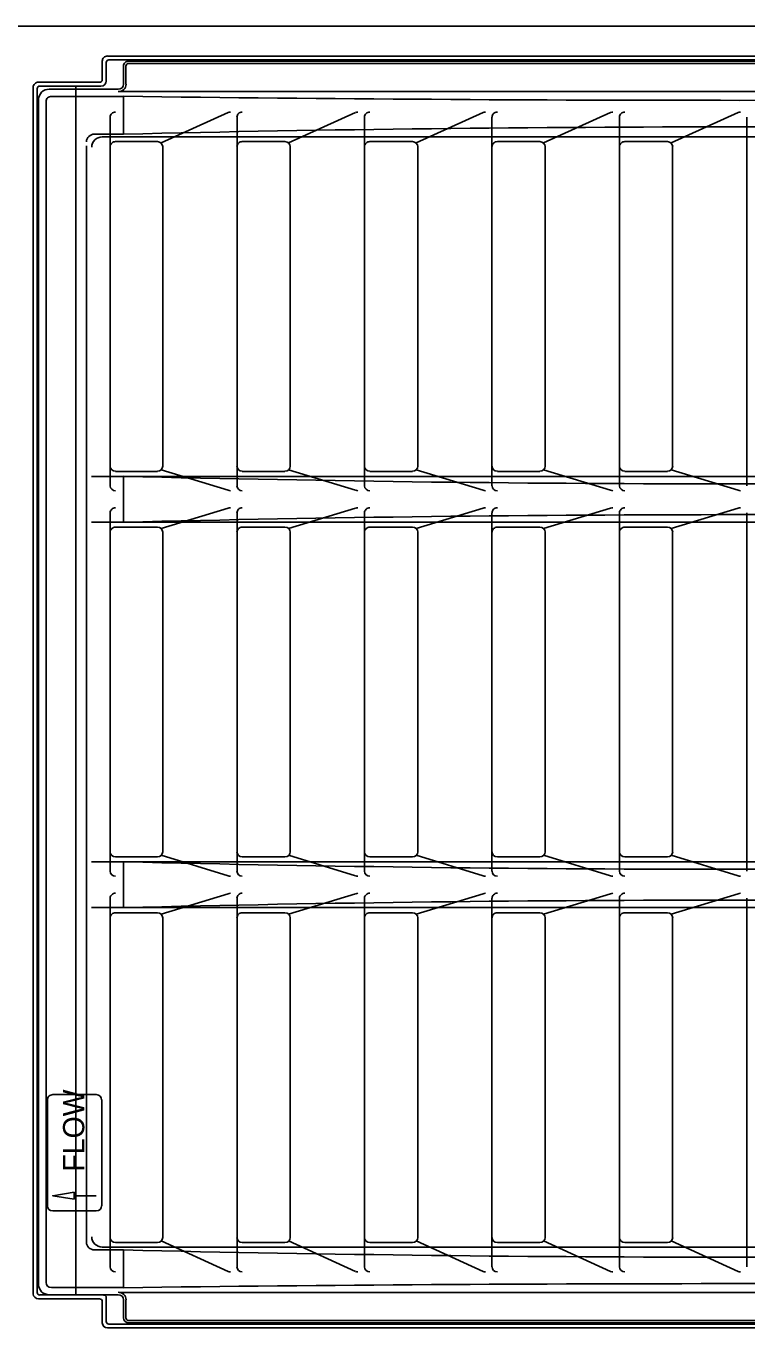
# Model space of a CAD drawing. Extents: x 2.4 to 9.7, y 1.1 to 11.2.
# Drawn here: x 7.421 to 8.009, y 5.384 to 6.445 of the extents above; entities that cross this region are included whole.
import ezdxf

# ---------------------------------------------------------------- set-up
doc = ezdxf.new("R2010")
doc.units = 0
doc.layers.add('DETL-LINE', color=7, linetype='Continuous')
doc.layers.add('DETL-NOTE', color=7, linetype='Continuous')

msp = doc.modelspace()

# ---------------------------------------------------------------- linework, layer by layer
at = {"layer": 'DETL-LINE'}
for p, q in [((7.4498, 6.4451), (6.8316, 6.4451)), ((7.4498, 6.4451), (8.068, 6.4451)), ((7.4831, 6.4013), (7.4831, 6.4166)), ((7.4863, 6.4003), (7.4863, 6.4155)), ((8.5179, 6.4207), (7.4874, 6.4207)), ((8.5168, 6.4176), (7.4885, 6.4176)), ((7.5024, 6.4125), (7.5024, 6.3977)), ((8.5006, 6.4146), (7.5047, 6.4146)), ((7.4268, 5.4117), (7.4268, 6.3952)), ((7.43, 5.4127), (7.43, 6.3941)), ((7.4809, 6.3993), (7.4311, 6.3993)), ((7.482, 6.3962), (7.4322, 6.3962)), ((7.4614, 6.3936), (7.4614, 6.3962)), ((7.4614, 5.4109), (7.4614, 6.3936)), ((8.5092, 6.3917), (7.4969, 6.3917)), ((7.4373, 5.4208), (7.4373, 6.3837)), ((7.5004, 6.3878), (7.4416, 6.3878)), ((7.5004, 6.3878), (7.5004, 6.357)), ((7.4702, 5.4536), (7.4702, 6.3475)), ((7.5004, 6.357), (7.4767, 6.357)), ((7.4831, 6.3547), (8.5222, 6.3547)), ((8.5309, 6.078), (7.4744, 6.078)), ((7.5004, 6.0407), (7.5004, 6.078)), ((8.5309, 6.0407), (7.4744, 6.0407)), ((8.5309, 5.7638), (7.4744, 5.7638)), ((7.5004, 5.7265), (7.5004, 5.7638)), ((8.5309, 5.7265), (7.4744, 5.7265)), ((7.5004, 5.4475), (7.4767, 5.4475)), ((7.4831, 5.4498), (8.5222, 5.4498)), ((7.5004, 5.4167), (7.5004, 5.4475)), ((7.5004, 5.4167), (7.4416, 5.4167)), ((8.5092, 5.4128), (7.4969, 5.4128)), ((7.4809, 5.4076), (7.4311, 5.4076)), ((7.4842, 5.4107), (7.4322, 5.4107)), ((7.4614, 5.4107), (7.4614, 5.4109)), ((7.4831, 5.3879), (7.4831, 5.4055)), ((7.4863, 5.389), (7.4863, 5.4086)), ((7.5024, 5.392), (7.5024, 5.4068)), ((8.5179, 5.3838), (7.4874, 5.3838)), ((8.5168, 5.3869), (7.4885, 5.3869)), ((8.5006, 5.3899), (7.5047, 5.3899))]:
    msp.add_line(p, q, dxfattribs=at)
for centre, major_axis, start_param, end_param in [((7.4874, 6.4166), (0.00433, 0), 1.570796, 3.141593), ((7.4885, 6.4155), (0.00216, 0), 1.570796, 3.141593), ((7.5047, 6.4125), (0.00229, 0), 1.570796, 3.141593), ((7.4809, 6.4013), (0.00216, 0), 4.712389, 6.283185), ((7.482, 6.4003), (0.00433, 0), 4.712389, 6.283185), ((7.4311, 6.3952), (0.00433, 0), 1.570796, 3.141593), ((7.4322, 6.3941), (0.00216, 0), 1.570796, 3.141593), ((7.4961, 6.3977), (0.00637, 0), 4.712389, 6.283185), ((7.4416, 6.3837), (0.00433, 0), 1.570796, 3.141593), ((8.0026, 40.9898), (36.4153, 0), 4.698596, 4.726182), ((8.0026, -12.9443), (20.3171, 0), 1.546073, 1.59552), ((7.4767, 6.3508), (0.00649, 0), 1.570796, 3.141593), ((7.4831, 6.3465), (0.00866, 0), 1.570796, 3.141593), ((8.0026, 24.5302), (19.4238, 0), 4.686528, 4.73825), ((8.0026, -12.4115), (19.4238, 0), 1.544936, 1.596657), ((8.0026, 24.216), (19.4238, 0), 4.686528, 4.73825), ((8.0026, -12.7257), (19.4238, 0), 1.544936, 1.596657), ((7.4831, 5.458), (0.00866, 0), 3.141593, 4.712389), ((7.4767, 5.4536), (0.00649, 0), 3.141593, 4.712389), ((8.0026, 24.7487), (20.3171, 0), 4.687666, 4.737112), ((7.4322, 5.4127), (0.00216, 0), 3.141593, 4.712389), ((7.4416, 5.4208), (0.00433, 0), 3.141593, 4.712389), ((7.4961, 5.4068), (0.00637, 0), 0, 1.570796), ((8.0026, -29.1853), (36.4153, 0), 1.557003, 1.584589), ((7.4311, 5.4117), (0.00433, 0), 3.141593, 4.712389), ((7.4809, 5.4055), (0.00216, 0), 0, 1.570796), ((7.4842, 5.4086), (0.00216, 0), 0, 1.570796), ((7.5047, 5.392), (0.00229, 0), 3.141593, 4.712389), ((7.4874, 5.3879), (0.00433, 0), 3.141593, 4.712389), ((7.4885, 5.389), (0.00216, 0), 3.141593, 4.712389)]:
    msp.add_ellipse(centre, major_axis=major_axis, ratio=0.950294, start_param=start_param, end_param=end_param, dxfattribs=at)
at = {"layer": 'DETL-NOTE'}
for p, q in [((7.5004, 6.4125), (7.5004, 6.3977)), ((7.5047, 6.4166), (8.5006, 6.4166)), ((7.5004, 6.4018), (7.5004, 6.3978)), ((7.4961, 6.3936), (7.4398, 6.3936)), ((7.4311, 5.4191), (7.4311, 6.3854)), ((7.4895, 6.3709), (7.4895, 6.1961)), ((7.5311, 6.3498), (7.5857, 6.3746)), ((7.5929, 6.3709), (7.5929, 6.1961)), ((7.635, 6.3498), (7.6896, 6.3746)), ((7.6968, 6.3709), (7.6968, 6.1961)), ((7.7389, 6.3498), (7.7935, 6.3746)), ((7.8007, 6.3709), (7.8007, 6.1961)), ((7.8428, 6.3498), (7.8974, 6.3746)), ((7.9047, 6.3709), (7.9047, 6.1961)), ((7.9468, 6.3498), (8.0014, 6.3746)), ((8.0086, 6.3709), (8.0086, 6.1961)), ((7.528, 6.351), (7.4938, 6.351)), ((7.5324, 6.3468), (7.5324, 6.1961)), ((7.632, 6.351), (7.5972, 6.351)), ((7.6363, 6.3468), (7.6363, 6.1961)), ((7.7359, 6.351), (7.7012, 6.351)), ((7.7402, 6.3468), (7.7402, 6.1961)), ((7.8398, 6.351), (7.8051, 6.351)), ((7.8441, 6.3468), (7.8441, 6.1961)), ((7.9437, 6.351), (7.909, 6.351)), ((7.948, 6.3468), (7.948, 6.1961)), ((7.4895, 6.0704), (7.4895, 6.1961)), ((7.5324, 6.0863), (7.5324, 6.1961)), ((7.5929, 6.0704), (7.5929, 6.1961)), ((7.6363, 6.0863), (7.6363, 6.1961)), ((7.6968, 6.0704), (7.6968, 6.1961)), ((7.7402, 6.0863), (7.7402, 6.1961)), ((7.8007, 6.0704), (7.8007, 6.1961)), ((7.8441, 6.0863), (7.8441, 6.1961)), ((7.9047, 6.0704), (7.9047, 6.1961)), ((7.948, 6.0863), (7.948, 6.1961)), ((8.0086, 6.0704), (8.0086, 6.1961)), ((7.528, 6.0821), (7.4938, 6.0821)), ((7.5311, 6.0834), (7.5857, 6.0667)), ((7.632, 6.0821), (7.5972, 6.0821)), ((7.635, 6.0834), (7.6896, 6.0667)), ((7.7359, 6.0821), (7.7012, 6.0821)), ((7.7389, 6.0834), (7.7935, 6.0667)), ((7.8398, 6.0821), (7.8051, 6.0821)), ((7.8428, 6.0834), (7.8974, 6.0667)), ((7.9437, 6.0821), (7.909, 6.0821)), ((7.9468, 6.0834), (8.0014, 6.0667)), ((7.5311, 6.0354), (7.5857, 6.0521)), ((7.635, 6.0354), (7.6896, 6.0521)), ((7.7389, 6.0354), (7.7935, 6.0521)), ((7.8428, 6.0354), (7.8974, 6.0521)), ((7.9468, 6.0354), (8.0014, 6.0521)), ((7.4895, 6.0483), (7.4895, 5.7561)), ((7.5929, 6.0483), (7.5929, 5.7561)), ((7.6968, 6.0483), (7.6968, 5.7561)), ((7.8007, 6.0483), (7.8007, 5.7561)), ((7.9047, 6.0483), (7.9047, 5.7561)), ((8.0086, 6.0483), (8.0086, 5.7561)), ((7.528, 6.0366), (7.4938, 6.0366)), ((7.5324, 6.0325), (7.5324, 5.772)), ((7.632, 6.0366), (7.5972, 6.0366)), ((7.6363, 6.0325), (7.6363, 5.772)), ((7.7359, 6.0366), (7.7012, 6.0366)), ((7.7402, 6.0325), (7.7402, 5.772)), ((7.8398, 6.0366), (7.8051, 6.0366)), ((7.8441, 6.0325), (7.8441, 5.772)), ((7.9437, 6.0366), (7.909, 6.0366)), ((7.948, 6.0325), (7.948, 5.772)), ((7.528, 5.7679), (7.4938, 5.7679)), ((7.5311, 5.7691), (7.5857, 5.7524)), ((7.632, 5.7679), (7.5972, 5.7679)), ((7.635, 5.7691), (7.6896, 5.7524)), ((7.7359, 5.7679), (7.7012, 5.7679)), ((7.7389, 5.7691), (7.7935, 5.7524)), ((7.8398, 5.7679), (7.8051, 5.7679)), ((7.8428, 5.7691), (7.8974, 5.7524)), ((7.9437, 5.7679), (7.909, 5.7679)), ((7.9468, 5.7691), (8.0014, 5.7524)), ((7.4895, 5.7341), (7.4895, 5.703)), ((7.5311, 5.7211), (7.5857, 5.7378)), ((7.5929, 5.7341), (7.5929, 5.703)), ((7.635, 5.7211), (7.6896, 5.7378)), ((7.6968, 5.7341), (7.6968, 5.703)), ((7.7389, 5.7211), (7.7935, 5.7378)), ((7.8007, 5.7341), (7.8007, 5.703)), ((7.8428, 5.7211), (7.8974, 5.7378)), ((7.9047, 5.7341), (7.9047, 5.703)), ((7.9468, 5.7211), (8.0014, 5.7378)), ((8.0086, 5.7341), (8.0086, 5.703)), ((7.528, 5.7223), (7.4938, 5.7223)), ((7.632, 5.7223), (7.5972, 5.7223)), ((7.7359, 5.7223), (7.7012, 5.7223)), ((7.8398, 5.7223), (7.8051, 5.7223)), ((7.9437, 5.7223), (7.909, 5.7223)), ((7.5324, 5.7182), (7.5324, 5.703)), ((7.6363, 5.7182), (7.6363, 5.703)), ((7.7402, 5.7182), (7.7402, 5.703)), ((7.8441, 5.7182), (7.8441, 5.703)), ((7.948, 5.7182), (7.948, 5.703)), ((7.4895, 5.4336), (7.4895, 5.703)), ((7.5324, 5.4576), (7.5324, 5.703)), ((7.5929, 5.4336), (7.5929, 5.703)), ((7.6363, 5.4576), (7.6363, 5.703)), ((7.6968, 5.4336), (7.6968, 5.703)), ((7.7402, 5.4576), (7.7402, 5.703)), ((7.8007, 5.4336), (7.8007, 5.703)), ((7.8441, 5.4576), (7.8441, 5.703)), ((7.9047, 5.4336), (7.9047, 5.703)), ((7.948, 5.4576), (7.948, 5.703)), ((8.0086, 5.4336), (8.0086, 5.703)), ((7.4427, 5.574), (7.4782, 5.574)), ((7.4384, 5.5699), (7.4384, 5.4834)), ((7.4826, 5.5699), (7.4826, 5.4834)), ((7.4601, 5.4916), (7.478, 5.4916)), ((7.4427, 5.4793), (7.4782, 5.4793)), ((7.528, 5.4535), (7.4938, 5.4535)), ((7.5311, 5.4547), (7.5857, 5.4298)), ((7.632, 5.4535), (7.5972, 5.4535)), ((7.635, 5.4547), (7.6896, 5.4298)), ((7.7359, 5.4535), (7.7012, 5.4535)), ((7.7389, 5.4547), (7.7935, 5.4298)), ((7.8398, 5.4535), (7.8051, 5.4535)), ((7.8428, 5.4547), (7.8974, 5.4298)), ((7.9437, 5.4535), (7.909, 5.4535)), ((7.9468, 5.4547), (8.0014, 5.4298)), ((7.4961, 5.4109), (7.4398, 5.4109)), ((7.5004, 5.392), (7.5004, 5.4068)), ((7.5004, 5.4027), (7.5004, 5.4067)), ((7.5047, 5.3879), (8.5006, 5.3879))]:
    msp.add_line(p, q, dxfattribs=at)
msp.add_lwpolyline([(7.4601, 5.4889), (7.4601, 5.4944), (7.4427, 5.4916)], close=True, dxfattribs=at)
for centre, major_axis, start_param, end_param in [((7.5047, 6.4125), (0.00433, 0), 1.570796, 3.141593), ((7.4398, 6.3854), (0.00866, 0), 1.570796, 3.141593), ((7.4961, 6.3977), (0.00433, 0), 4.712389, 6.283185), ((7.4938, 6.3709), (0.00433, 0), 1.570796, 3.141593), ((7.5876, 6.3709), (0.00433, 0), 1.570796, 2.018093), ((7.5972, 6.3709), (0.00433, 0), 1.570796, 3.141593), ((7.6915, 6.3709), (0.00433, 0), 1.570796, 2.018093), ((7.7012, 6.3709), (0.00433, 0), 1.570796, 3.141593), ((7.7954, 6.3709), (0.00433, 0), 1.570796, 2.018093), ((7.8051, 6.3709), (0.00433, 0), 1.570796, 3.141593), ((7.8993, 6.3709), (0.00433, 0), 1.570796, 2.018093), ((7.909, 6.3709), (0.00433, 0), 1.570796, 3.141593), ((8.0032, 6.3709), (0.00433, 0), 1.570796, 2.018093), ((7.4938, 6.3468), (0.00433, 0), 1.570796, 3.141593), ((7.528, 6.3468), (0.00433, 0), 0, 1.570796), ((7.5972, 6.3468), (0.00433, 0), 1.570796, 3.141593), ((7.632, 6.3468), (0.00433, 0), 0, 1.570796), ((7.7012, 6.3468), (0.00433, 0), 1.570796, 3.141593), ((7.7359, 6.3468), (0.00433, 0), 0, 1.570796), ((7.8051, 6.3468), (0.00433, 0), 1.570796, 3.141593), ((7.8398, 6.3468), (0.00433, 0), 0, 1.570796), ((7.909, 6.3468), (0.00433, 0), 1.570796, 3.141593), ((7.9437, 6.3468), (0.00433, 0), 0, 1.570796), ((7.4938, 6.0863), (0.00433, 0), 3.141593, 4.712389), ((7.528, 6.0863), (0.00433, 0), 4.712389, 6.283185), ((7.5972, 6.0863), (0.00433, 0), 3.141593, 4.712389), ((7.632, 6.0863), (0.00433, 0), 4.712389, 6.283185), ((7.7012, 6.0863), (0.00433, 0), 3.141593, 4.712389), ((7.7359, 6.0863), (0.00433, 0), 4.712389, 6.283185), ((7.8051, 6.0863), (0.00433, 0), 3.141593, 4.712389), ((7.8398, 6.0863), (0.00433, 0), 4.712389, 6.283185), ((7.909, 6.0863), (0.00433, 0), 3.141593, 4.712389), ((7.9437, 6.0863), (0.00433, 0), 4.712389, 6.283185), ((7.4938, 6.0704), (0.00433, 0), 3.141593, 4.712389), ((7.5876, 6.0704), (0.00433, 0), 4.265092, 4.712389), ((7.5972, 6.0704), (0.00433, 0), 3.141593, 4.712389), ((7.6915, 6.0704), (0.00433, 0), 4.265092, 4.712389), ((7.7012, 6.0704), (0.00433, 0), 3.141593, 4.712389), ((7.7954, 6.0704), (0.00433, 0), 4.265092, 4.712389), ((7.8051, 6.0704), (0.00433, 0), 3.141593, 4.712389), ((7.8993, 6.0704), (0.00433, 0), 4.265092, 4.712389), ((7.909, 6.0704), (0.00433, 0), 3.141593, 4.712389), ((8.0032, 6.0704), (0.00433, 0), 4.265092, 4.712389), ((7.4938, 6.0483), (0.00433, 0), 1.570796, 3.141593), ((7.5876, 6.0483), (0.00433, 0), 1.570796, 2.018093), ((7.5972, 6.0483), (0.00433, 0), 1.570796, 3.141593), ((7.6915, 6.0483), (0.00433, 0), 1.570796, 2.018093), ((7.7012, 6.0483), (0.00433, 0), 1.570796, 3.141593), ((7.7954, 6.0483), (0.00433, 0), 1.570796, 2.018093), ((7.8051, 6.0483), (0.00433, 0), 1.570796, 3.141593), ((7.8993, 6.0483), (0.00433, 0), 1.570796, 2.018093), ((7.909, 6.0483), (0.00433, 0), 1.570796, 3.141593), ((8.0032, 6.0483), (0.00433, 0), 1.570796, 2.018093), ((7.4938, 6.0325), (0.00433, 0), 1.570796, 3.141593), ((7.528, 6.0325), (0.00433, 0), 0, 1.570796), ((7.5972, 6.0325), (0.00433, 0), 1.570796, 3.141593), ((7.632, 6.0325), (0.00433, 0), 0, 1.570796), ((7.7012, 6.0325), (0.00433, 0), 1.570796, 3.141593), ((7.7359, 6.0325), (0.00433, 0), 0, 1.570796), ((7.8051, 6.0325), (0.00433, 0), 1.570796, 3.141593), ((7.8398, 6.0325), (0.00433, 0), 0, 1.570796), ((7.909, 6.0325), (0.00433, 0), 1.570796, 3.141593), ((7.9437, 6.0325), (0.00433, 0), 0, 1.570796), ((7.4938, 5.772), (0.00433, 0), 3.141593, 4.712389), ((7.528, 5.772), (0.00433, 0), 4.712389, 6.283185), ((7.5972, 5.772), (0.00433, 0), 3.141593, 4.712389), ((7.632, 5.772), (0.00433, 0), 4.712389, 6.283185), ((7.7012, 5.772), (0.00433, 0), 3.141593, 4.712389), ((7.7359, 5.772), (0.00433, 0), 4.712389, 6.283185), ((7.8051, 5.772), (0.00433, 0), 3.141593, 4.712389), ((7.8398, 5.772), (0.00433, 0), 4.712389, 6.283185), ((7.909, 5.772), (0.00433, 0), 3.141593, 4.712389), ((7.9437, 5.772), (0.00433, 0), 4.712389, 6.283185), ((7.4938, 5.7561), (0.00433, 0), 3.141593, 4.712389), ((7.5876, 5.7561), (0.00433, 0), 4.265092, 4.712389), ((7.5972, 5.7561), (0.00433, 0), 3.141593, 4.712389), ((7.6915, 5.7561), (0.00433, 0), 4.265092, 4.712389), ((7.7012, 5.7561), (0.00433, 0), 3.141593, 4.712389), ((7.7954, 5.7561), (0.00433, 0), 4.265092, 4.712389), ((7.8051, 5.7561), (0.00433, 0), 3.141593, 4.712389), ((7.8993, 5.7561), (0.00433, 0), 4.265092, 4.712389), ((7.909, 5.7561), (0.00433, 0), 3.141593, 4.712389), ((8.0032, 5.7561), (0.00433, 0), 4.265092, 4.712389), ((7.4938, 5.7341), (0.00433, 0), 1.570796, 3.141593), ((7.5876, 5.7341), (0.00433, 0), 1.570796, 2.018093), ((7.5972, 5.7341), (0.00433, 0), 1.570796, 3.141593), ((7.6915, 5.7341), (0.00433, 0), 1.570796, 2.018093), ((7.7012, 5.7341), (0.00433, 0), 1.570796, 3.141593), ((7.7954, 5.7341), (0.00433, 0), 1.570796, 2.018093), ((7.8051, 5.7341), (0.00433, 0), 1.570796, 3.141593), ((7.8993, 5.7341), (0.00433, 0), 1.570796, 2.018093), ((7.909, 5.7341), (0.00433, 0), 1.570796, 3.141593), ((8.0032, 5.7341), (0.00433, 0), 1.570796, 2.018093), ((7.4938, 5.7182), (0.00433, 0), 1.570796, 3.141593), ((7.528, 5.7182), (0.00433, 0), 0, 1.570796), ((7.5972, 5.7182), (0.00433, 0), 1.570796, 3.141593), ((7.632, 5.7182), (0.00433, 0), 0, 1.570796), ((7.7012, 5.7182), (0.00433, 0), 1.570796, 3.141593), ((7.7359, 5.7182), (0.00433, 0), 0, 1.570796), ((7.8051, 5.7182), (0.00433, 0), 1.570796, 3.141593), ((7.8398, 5.7182), (0.00433, 0), 0, 1.570796), ((7.909, 5.7182), (0.00433, 0), 1.570796, 3.141593), ((7.9437, 5.7182), (0.00433, 0), 0, 1.570796), ((7.4427, 5.5699), (0.00433, 0), 1.570796, 3.141593), ((7.4782, 5.5699), (0.00433, 0), 0, 1.570796), ((7.4427, 5.4834), (0.00433, 0), 3.141593, 4.712389), ((7.4782, 5.4834), (0.00433, 0), 4.712389, 6.283185), ((7.4938, 5.4576), (0.00433, 0), 3.141593, 4.712389), ((7.528, 5.4576), (0.00433, 0), 4.712389, 6.283185), ((7.5972, 5.4576), (0.00433, 0), 3.141593, 4.712389), ((7.632, 5.4576), (0.00433, 0), 4.712389, 6.283185), ((7.7012, 5.4576), (0.00433, 0), 3.141593, 4.712389), ((7.7359, 5.4576), (0.00433, 0), 4.712389, 6.283185), ((7.8051, 5.4576), (0.00433, 0), 3.141593, 4.712389), ((7.8398, 5.4576), (0.00433, 0), 4.712389, 6.283185), ((7.909, 5.4576), (0.00433, 0), 3.141593, 4.712389), ((7.9437, 5.4576), (0.00433, 0), 4.712389, 6.283185), ((7.4938, 5.4336), (0.00433, 0), 3.141593, 4.712389), ((7.5876, 5.4336), (0.00433, 0), 4.265092, 4.712389), ((7.5972, 5.4336), (0.00433, 0), 3.141593, 4.712389), ((7.6915, 5.4336), (0.00433, 0), 4.265092, 4.712389), ((7.7012, 5.4336), (0.00433, 0), 3.141593, 4.712389), ((7.7954, 5.4336), (0.00433, 0), 4.265092, 4.712389), ((7.8051, 5.4336), (0.00433, 0), 3.141593, 4.712389), ((7.8993, 5.4336), (0.00433, 0), 4.265092, 4.712389), ((7.909, 5.4336), (0.00433, 0), 3.141593, 4.712389), ((8.0032, 5.4336), (0.00433, 0), 4.265092, 4.712389), ((7.4398, 5.4191), (0.00866, 0), 3.141593, 4.712389), ((7.4961, 5.4068), (0.00433, 0), 0, 1.570796), ((7.5047, 5.392), (0.00433, 0), 3.141593, 4.712389)]:
    msp.add_ellipse(centre, major_axis=major_axis, ratio=0.950294, start_param=start_param, end_param=end_param, dxfattribs=at)

# ---------------------------------------------------------------- texts
msp.add_text('FLOW', height=0.01732, rotation=90, dxfattribs=at).set_placement((7.4684, 5.5113))

doc.saveas('drawing.dxf')
